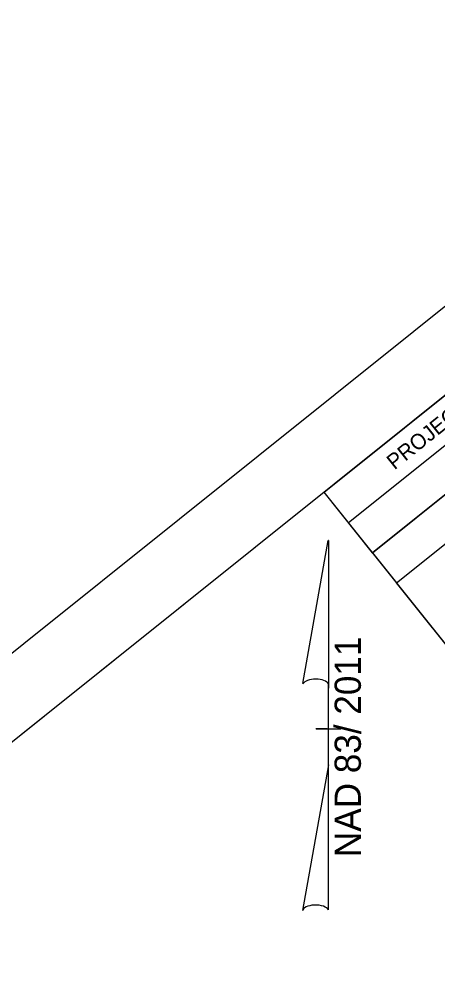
# Model space of a CAD drawing. Extents: x 472510 to 474509, y 505091 to 506998.
# Drawn here: x 473570.5 to 473706, y 506685.1 to 506998.1 of the extents above; entities that cross this region are included whole.
import ezdxf

# ---------------------------------------------------------------- set-up
doc = ezdxf.new("R2010")
doc.units = 0
for name, color, linetype in [('Prop North Arrow NAD83 for Plan Sheets CELL', 7, 'Continuous'), ('Sheet Clip Boundary CELL', 7, 'Continuous'), ('Sheet Plan CELL', 7, 'Continuous'), ('Sheet Plot Border Outside CELL', 7, 'Continuous')]:
    doc.layers.add(name, color=color, linetype=linetype)

msp = doc.modelspace()

# ---------------------------------------------------------------- linework, layer by layer
at = {"layer": 'Prop North Arrow NAD83 for Plan Sheets CELL'}
for p, q in [((473662.37, 506782.95), (473670.57, 506829.3)), ((473670.62, 506829.3), (473670.57, 506829.3)), ((473670.62, 506829.3), (473670.57, 506829.3)), ((473670.62, 506829.3), (473670.62, 506781.5)), ((473670.62, 506756.7), (473670.62, 506782.9)), ((473670.62, 506781.5), (473670.62, 506782.85)), ((473666.62, 506768.3), (473666.57, 506768.3)), ((473670.17, 506768.3), (473666.62, 506768.3)), ((473666.67, 506768.3), (473674.67, 506768.3)), ((473670.62, 506756.7), (473662.27, 506709.45)), ((473670.67, 506709.65), (473670.62, 506756.7))]:
    msp.add_line(p, q, dxfattribs=at)
for centre, start_param, end_param in [((473666.5, 506782.45), 0.216388, 2.908219), ((473666.5, 506709.28), 0.201328, 3.141593)]:
    msp.add_ellipse(centre, major_axis=(4.23, -0.03), ratio=0.461098, start_param=start_param, end_param=end_param, dxfattribs=at)
at = {"layer": 'Sheet Clip Boundary CELL'}
msp.add_lwpolyline([(473777.72, 506709.45), (473669.28, 506844.95), (472855.07, 506193.32), (472968.62, 506051.1), (472829.89, 505940.08), (472768.98, 505889.4), (473229.88, 505313.51), (473287.27, 505310.53), (473108.82, 505533.5), (473372.02, 505744.15), (473550.47, 505521.18), (474139.22, 505988.54), (474128.73, 506014.5), (474324.31, 506183.29), (473855.21, 506771.46)], close=True, dxfattribs=at)
at = {"layer": 'Sheet Plan CELL'}
for p, q in [((473677.09, 506835.14), (473833.29, 506960.13)), ((473684.94, 506825.36), (473841.1, 506950.37)), ((473684.94, 506825.36), (473841.1, 506950.37)), ((473684.94, 506825.36), (473692.74, 506815.61))]:
    msp.add_line(p, q, dxfattribs=at)
for points in [[(473825.47, 506969.95), (472654.33, 506032.66), (473310.42, 505212.87), (474481.55, 506150.16)], [(473669.26, 506844.95), (473825.47, 506969.95), (473841.1, 506950.37), (473684.94, 506825.36)], [(473692.74, 506815.61), (473770.85, 506878.13), (473841.16, 506790.28), (473763.04, 506727.79)]]:
    msp.add_lwpolyline(points, close=True, dxfattribs=at)
at = {"layer": 'Sheet Plot Border Outside CELL'}
msp.add_lwpolyline([(473194.51, 505091.27), (474508.89, 506143.2), (473824.68, 506998.12), (472510.29, 505946.18)], close=True, dxfattribs=at)

# ---------------------------------------------------------------- texts
at = {"layer": 'Prop North Arrow NAD83 for Plan Sheets CELL'}
msp.add_text('NAD 83/ 2011', height=8.5, rotation=90, dxfattribs=at).set_placement((473681.14, 506726.78))
at = {"layer": 'Sheet Plan CELL'}
msp.add_text('PROJECT REFERENCE NO.', height=5.0001, rotation=38.6712, dxfattribs=at).set_placement((473692.04, 506852.01))

doc.saveas('drawing.dxf')
